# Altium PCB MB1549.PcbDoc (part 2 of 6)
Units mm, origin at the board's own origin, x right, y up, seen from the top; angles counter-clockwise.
Board outline 70 x 133.34 mm, 6 copper layers (Top Layer, Signal Layer 1, Signal Layer 2, Signal Layer 3, Signal Layer 4, Bottom Layer), stack 1.57 mm thick; 289 components, 250 nets, 1288 pads, 875 vias.
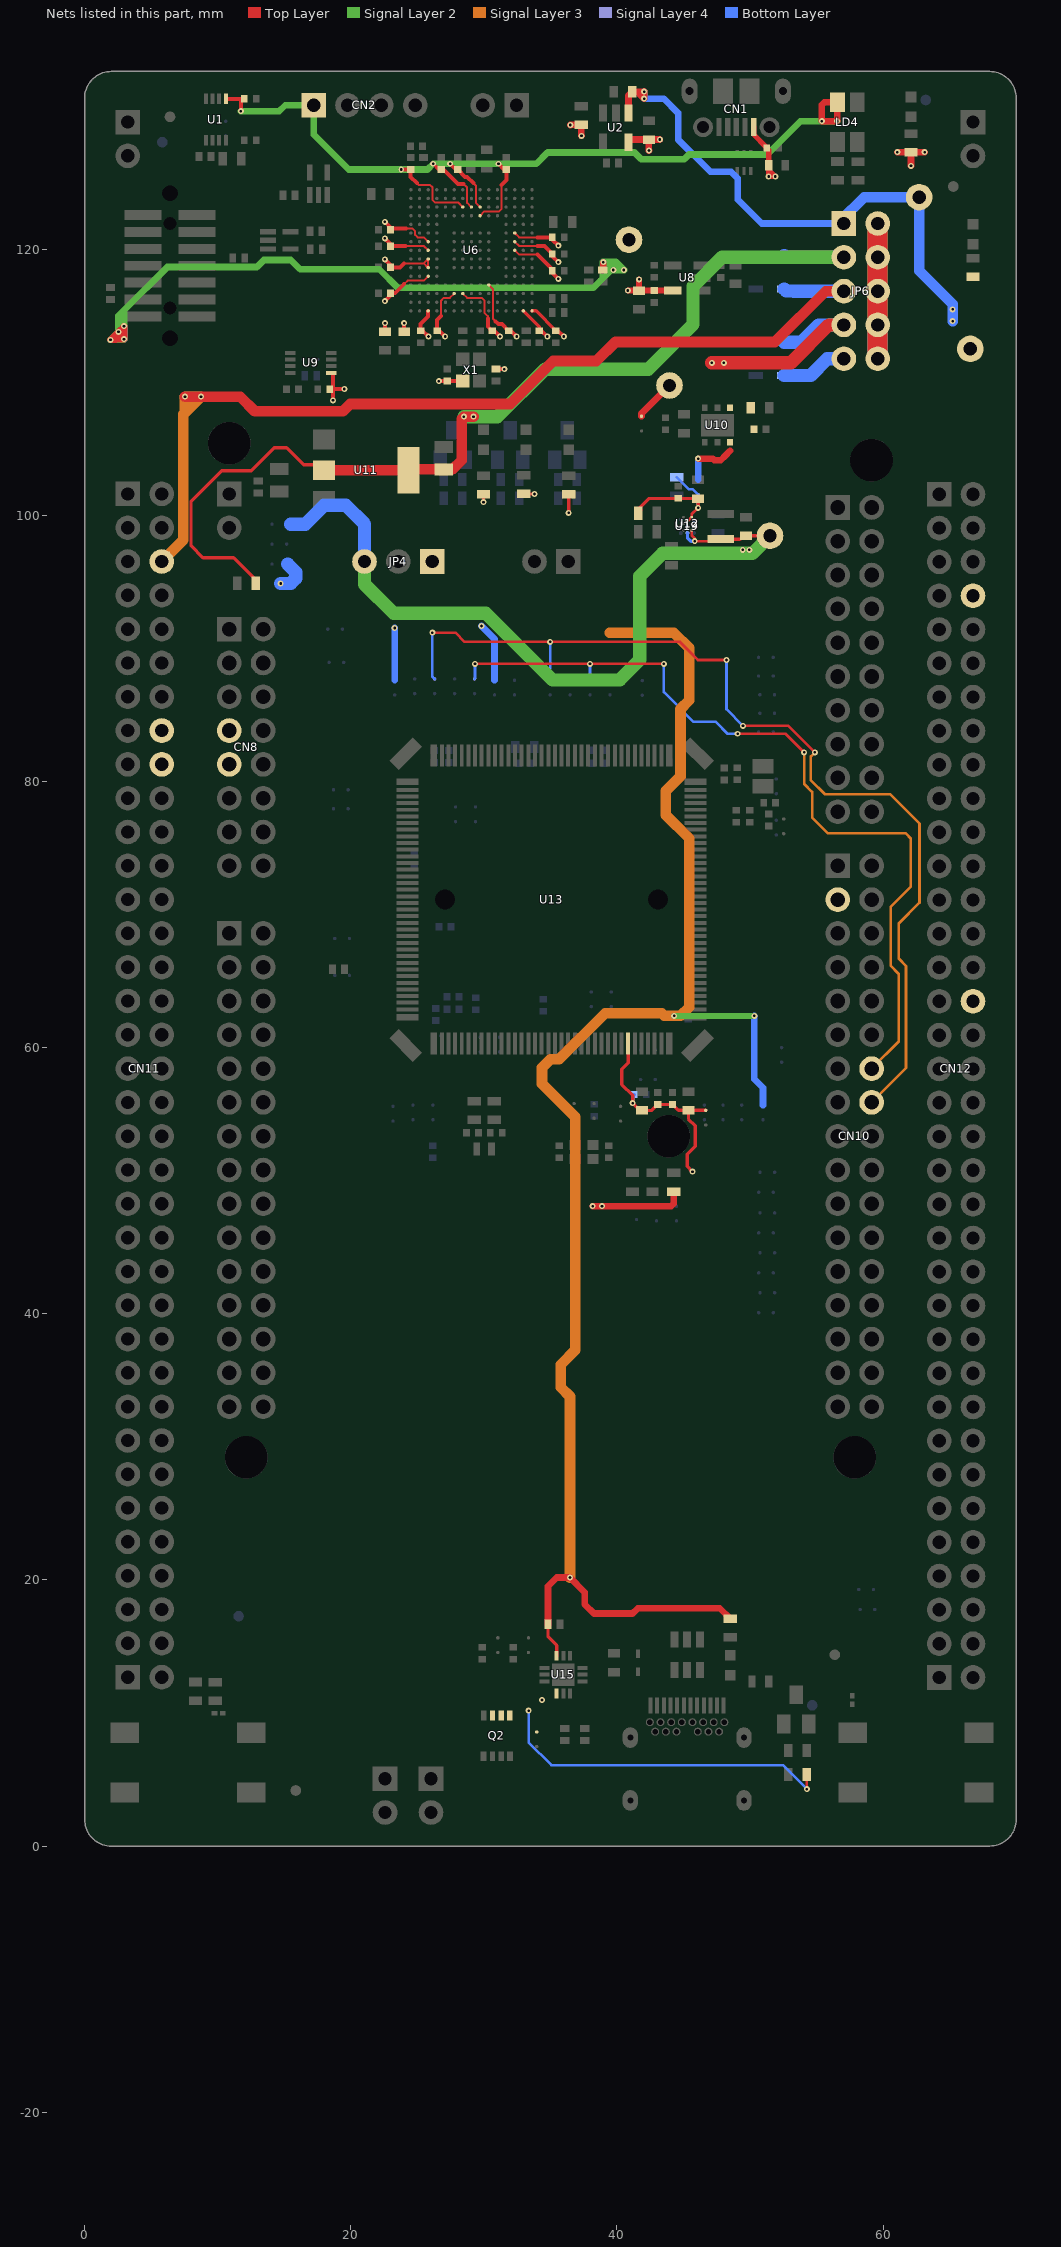
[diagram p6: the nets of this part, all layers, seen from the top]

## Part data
B1: library part MCD-00002, "Non-Open Push-Button 0.1A 24V BLUE", Manufacturer=WEALTHMETAL, Manufacturer_Part_Number=TD0341X-G01-BLU
B2: library part MCD-00001, "Non-Open Push-Button 0.1A 24V BLACK", Manufacturer=WEALTHMETAL, Manufacturer_Part_Number=TD0341X-G01-BLA
C1 C3 C18 C23 C34 C38 C39 C53 C54: library part MCD-00010, "Capacitor, MLCC, 1uF, 16V, X5R, 10%, 0603, T=0,8mm", Manufacturer=YAGEO, Manufacturer_Part_Number=CC0603KRX5R7BB105, Package=C0603
C2 C4 C8 C9 C10 C11 C14 C15 C16 C17 C20 C21 C22 C24 C25 C26 C27 C28 C29 C30 C31 C32 C35 C36 C37 C40 C41 C45 C52 C55 C56 C65 C68 C69 C70 C71 C72 C73 C74 C75 C76 C77 C79 C80 C81 C83 C84: library part MCD-00006, "Capacitor, MLCC, 100nF, 16V, X7R, 10%, 0402, T=0.5mm", Alternate_Manufacturer=MURATA, Alternate_Manufacturer_Part_Number=GCM155R71C104KA55D, Manufacturer=YAGEO, Manufacturer_Part_Number=CC0402KRX7R7BB104, Package=C0402
C5: library part MCD-00016, "Capacitor, MLCC, 20pF, 50V, NPO, 5%, 0402, T=0,5mm", Manufacturer=YAGEO, Manufacturer_Part_Number=CC0402JRNPO9BN200, Package=C0402
C6 C49: library part MCD-00205, "Capacitor, MLCC, 100pF, 50V, NPO, 5%, 0402, T=0,5mm", Manufacturer=YAGEO, Manufacturer_Part_Number=CC0402JRNPO9BN101, Package=C0402
C7 C12 C13: library part MCD-00012, "Capacitor, MLCC, 2.2uF, 10V, X5R, 10%, 0603, T=0,8mm", Alternate_Manufacturer=KEMET, Alternate_Manufacturer_Part_Number=C0603C225K8PACTU, Manufacturer=YAGEO, Manufacturer_Part_Number=CC0603KRX5R6BB225, Package=C0603
C19: library part MCD-00011, "Capacitor, MLCC, 10nF, 16V, X7R, 10%, 0402, T=0.5mm", Manufacturer=YAGEO, Manufacturer_Part_Number=CC0402KRX7R7BB103, Package=C0402
C33 C66: library part MCD-00009, "Capacitor, MLCC, 4.7uF, 16V, X5R, 10%, 0603, T=0.8mm", Manufacturer=YAGEO, Manufacturer_Part_Number=CC0603KRX5R7BB475, Package=C0603
C42 C43: library part MCD-00014, "Capacitor, MLCC, 10uF, 25V, X5R, 10%, 0805, T=0,85mm", Manufacturer=YAGEO, Manufacturer_Part_Number=CC0805KRX5R8BB106, Package=C0805
C44 C46: library part MCD-00243, "Capacitor, MLCC, 10uF, 6V3, X5R, 10%, 0603, T=0,8mm", Manufacturer=YAGEO, Manufacturer_Part_Number=CC0603KRX5R5BB106, Package=C0603
C47 C48 C78 C82: library part MCD-01823, "Capacitor,MLCC,2.2uF,6V3,X5R,10%,0402,T=0.5", Manufacturer=MURATA, Manufacturer_Part_Number=GRM155R60J225KE95D, Package=C0402
C50 C51 C67: library part MCD-01355, "Capacitor, MLCC, 10uF, 4V, X5R, 20%, 0402, T=0,5mm", Manufacturer=MURATA, Manufacturer_Part_Number=GRM155R60G106ME44, Package=C0402
C57 C58: library part MCD-01599, "Capacitor, MLCC, 1.8pF, 50V, NPO, +/-0.1pF, 0402, T=0.5mm", Manufacturer=YAGEO, Manufacturer_Part_Number=CC0402BRNPO9BN1R3, Package=C0402
C59 C60: library part MCD-00674, "Capacitor, MLCC, 6.8pF, 50V, NPO, +-0.25pF, 0402, T=0.5mm", Manufacturer=YAGEO, Manufacturer_Part_Number=CC0402CRNPO9BN6R8, Package=C0402
C61: library part MCD-00637, "Capacitor, MLCC, 10pF, 50V, NPO, 5%, 0603, T=0,8mm", Manufacturer=YAGEO, Manufacturer_Part_Number=CC0603JRNPO9BN100, Package=C0603
C62 C63: library part MCD-01579, "Capacitor, MLCC, 330pF, 50V, NPO, +/-5%, 0402, T=0,5mm", Manufacturer=YAGEO, Manufacturer_Part_Number=CC0402JRNPO9BN331, Package=C0402
C64: library part MCD-01099, "Capacitor,100nF,50V,X7R,10%,0603", Manufacturer=YAGEO, Manufacturer_Part_Number=CC0603KRX7R9BB104, Package=C0603
CN1: library part MCD-00028, "USB-MICRO-B, 0.65mm, RA, SMT, Bottom Mount,", Manufacturer=MOLEX, Manufacturer_Part_Number=1050170001
CN2: library part MCD-00029, "Header, 4x1, 2,54mm, VR, TH, Height 5.84mm/2.54mm", Manufacturer=SAMTEC, Manufacturer_Part_Number=TSW-104-07-x-S
CN3 CN4 CN13 CN14: library part MCD-00214, "Header, 2x1, 2,54mm, VR, TH, Height 5.84mm/10.16mm", Manufacturer=SAMTEC, Manufacturer_Part_Number=TSW-102-09-x-S
CN5: library part MCD-01226, "Header 5x2, 1.27mm, Dual row, Straight, Surface mount, vertical male connector. 3.05mm lead. Mates with FFSD connector. Footprint compatible with FTSH-107-01-L-DV,-K,-A,-P,-ES (STDC14 MEDIUM)", Alternate_Manufacturer=JIUBABA, Alternate_Manufacturer_Part_Number=P127B-2x05MGF-079-1A, Manufacturer=SAMTEC, Manufacturer_Part_Number=FTSH-105-01-L-DV-K
CN7: library part MCD-01039, "Socket, 10x2, 2.54mm, VR, TH, Height 8.51mm/10mm, Low insertion force.", Manufacturer=SAMTEC, Manufacturer_Part_Number=SSW-110-23-x-D
CN8: library part MCD-01037, "Socket, 8x2, 2.54mm, VR, TH, Height 8.51mm/10mm, Low insertion force.", Manufacturer=SAMTEC, Manufacturer_Part_Number=SSW-108-23-x-D
CN9: library part MCD-01040, "Socket, 15x2, 2.54mm, VR, TH, Height 8.51mm/10mm, Low insertion force.", Manufacturer=SAMTEC, Manufacturer_Part_Number=SSW-115-23-x-D
CN10: library part MCD-01041, "Socket, 17x2, 2.54mm, VR, TH, Height 8.51mm/10mm, Low insertion force", Manufacturer=SAMTEC, Manufacturer_Part_Number=SSW-117-23-x-D
CN11 CN12: library part MCD-01210, "Header, 35x2, 2,54mm, VR, TH, Height 5.84mm/2.54mm", Manufacturer=SAMTEC, Manufacturer_Part_Number=TSW-135-07-G-D
CN15: library part MCD-01108, "USB tyce C certified receptacle for 1.6mm pcb height", Manufacturer="CHANT SINCERE (COXOC)", Manufacturer_Part_Number=317JD24BZTF3K3C3
D1: library part MCD-01677, "Small signal Schottky diodes", Manufacturer=STMICROELECTRONICS, Manufacturer_Part_Number=BAT54KFILM, Package=SOD-523
D2 D3 D4 D5: library part MCD-00034, Manufacturer=STMICROELECTRONICS
HW101: library part MCD-00235, "Sticker to mention board reference + serial number", Manufacturer=n/a
HW102: library part MCD-00547, "Sticker to mention board CPN code", Manufacturer=n/a
JP1 JP7 JP8: library part MCD-00045, "Header, 2x1, 2,54mm, VR, TH, Height 5.84mm/2.54mm", Alternate_Manufacturer="JIUBABA; LIANYI", Alternate_Manufacturer_Part_Number=313102S111116;313102S111116, Manufacturer=SAMTEC, Manufacturer_Part_Number=TSW-102-07-x-S
JP2: library part MCD-00683, "Header, 2x1, 2,54mm, VR, TH, Height 5.84mm/2.54mm - Shunt Fitted by default", Alternate_Manufacturer=LIANYI, Alternate_Manufacturer_Part_Number=313102S111116, Manufacturer=SAMTEC, Manufacturer_Part_Number=TSW-102-07-x-S
JP4: library part MCD-00684, "Header, 3x1, 2,54mm, VR, TH, Height 5.84mm/2.54mm - Shunt Fitted 1-2 by default", Manufacturer=SAMTEC, Manufacturer_Part_Number=TSW-103-07-F-S
JP5: library part MCD-00683, "Header, 2x1, 2,54mm, VR, TH, Height 5.84mm/2.54mm - Shunt Fitted by default", Manufacturer=SAMTEC, Manufacturer_Part_Number=TSW-102-07-x-S
JP6: library part MCD-01203, "Header, 5x2, 2,54mm, VR, TH, Height 5.84mm/2.54mm - Shunt Fitted 1-2", Manufacturer=SAMTEC, Manufacturer_Part_Number=TSW-105-07-x-D
L1: library part MCD-00240, "FIXED IND 2.2UH 2.6A 100 mOHM 20% SMD", Manufacturer=TDK, Manufacturer_Part_Number=VLS252010HBX-2R2M-1
L2: library part MCD-01060, "Inductor, 2.2uH, 20%, Isat 0.7A, DCR 0.156Ohm, 0805", Manufacturer=MURATA, Manufacturer_Part_Number=LQM21PN2R2MGH, Package=L0805
LD1 LD5 LD7: library part MCD-00050, "LED, Green, 0603", Manufacturer=EVERLIGHT, Manufacturer_Part_Number=19-213SYGC/S530-E2/TR8, Package="LED 0603"
LD2: library part MCD-00584, "LED Blue, 0603 SMD, 3.3 V Forward Voltage", Manufacturer=VISHAY, Manufacturer_Part_Number=VLMB1300-GS08, Package="LED 0603"
LD3 LD6: library part MCD-00049, "LED, Red, 0603", Manufacturer=EVERLIGHT, Manufacturer_Part_Number=19-213-R6C-AP1Q2B/3T, Package="LED 0603"
LD4: library part MCD-00051, "LED Bicolor", Alternate_Manufacturer=EVERLUCK, Alternate_Manufacturer_Part_Number=LE-RGW35280, Manufacturer="AVAGO TECHNOLOGIES", Manufacturer_Part_Number=HSMF-A201-A00J1
Q1 Q3 Q4 Q5: library part MCD-00073, "NPN Bipolar Transistor", Manufacturer=NXP, Manufacturer_Part_Number=BSR14
Q2: library part MCD-01810, "N-channel 30 V, 6 mΩ typ, 11 A STripFET™ H6, Power MOSFET in a PowerFLAT™ 3.3x3.3 package", Manufacturer=STMICROELECTRONICS, Package="PowerFLAT 3.3x3.3"
R1 R4 R38 R45 R46 R47: library part MCD-00223, "Resistor,100K,0603,1%,1/10W", Manufacturer=YAGEO, Manufacturer_Part_Number=RC0603FR-07100KL, Package=R0603
R2 R14 R24 R30: library part MCD-00070, "Resistor,1K,0603,1%,1/10W", Manufacturer=YAGEO, Manufacturer_Part_Number=RC0603FR-071KL, Package=R0603
R3 R10 R11 R12 R13 R26: library part MCD-00481, "Resistor,47R,0402,1%,1/16W", Manufacturer=YAGEO, Manufacturer_Part_Number=RC0402FR-0747RL, Package=R0402
R5 R17 R20 R44: library part MCD-00067, "Resistor,100R,0402,1%,1/16W", Manufacturer=YAGEO, Manufacturer_Part_Number=RC0402FR-07100RL, Package=R0402
R6: library part MCD-00185, "Resistor,3K,0402,1%,1/16W", Manufacturer=YAGEO, Manufacturer_Part_Number=RC0402FR-073KL, Package=R0402
R7 R8 R39: library part MCD-00197, "Resistor,330R,0603,1%,1/10W", Manufacturer=YAGEO, Manufacturer_Part_Number=RC0603FR-07330RL, Package=R0603
R9 R21 R22 R31 R37 R40: library part MCD-00053, "Resistor,10K,0402,1%,1/16W", Manufacturer=YAGEO, Manufacturer_Part_Number=RC0402FR-0710KL, Package=R0402
R15 R18 R19: library part MCD-00065, "Resistor,4K7,0402,1%,1/16W", Alternate_Manufacturer=YAGEO, Alternate_Manufacturer_Part_Number=RT0402FRE074K7L, Manufacturer_Part_Number=RC0402FR-074K7L, Package=R0402
R16 R41: library part MCD-00055, "Resistor,2K7,0402,1%,1/16W", Manufacturer=YAGEO, Manufacturer_Part_Number=RC0402FR-072K7L, Package=R0402
R23: library part MCD-00508, "Resistor,680R,0603,1%,1/10W", Manufacturer=YAGEO, Manufacturer_Part_Number=RC0603FR-07680RL, Package=R0603
R25 R36: library part MCD-00225, "Resistor,510R,0603,1%,1/10W", Manufacturer=YAGEO, Manufacturer_Part_Number=RC0603FR-07510RL, Package=R0603
R27 R28 R32 R33 R48 R52: library part MCD-00056, "Resistor,0R,0603,5%,1/10W", Manufacturer=YAGEO, Manufacturer_Part_Number=RC0603JR-070RL, Package=R0603
R29: library part MCD-00242, "Resistor,19K6,0603,1%,1/10W", Manufacturer=YAGEO, Manufacturer_Part_Number=RC0603FR-0719K6L, Package=R0603
R34: library part MCD-01171, "Resistor,49K9,0603,1%", Manufacturer=YAGEO, Manufacturer_Part_Number=RC0603FR-0749K9L, Package=R0603
R35: library part MCD-00458, "Resistor,330K,0603,1%,1/10W", Manufacturer=YAGEO, Manufacturer_Part_Number=RC0603FR-07330KL, Package=R0603
R42: library part MCD-00430, "Resistor,22K,0603,1%,1/10W", Manufacturer=YAGEO, Manufacturer_Part_Number=RC0603FR-0722KL, Package=R0603
R43 R49 R50 R51: library part MCD-00222, "Resistor,47K,0603,1%,1/10W", Manufacturer=YAGEO, Manufacturer_Part_Number=RC0603FR-0747KL, Package=R0603
SB1 SB2 SB3 SB4 SB5 SB6 SB7 SB8 SB9 SB10 SB13 SB14 SB15 SB16 SB17 SB18 SB19 SB20 SB21 SB22 SB23 SB24 SB25 SB26 SB27 SB28 SB29 SB30 SB31 SB32 SB33 SB34 SB35 SB36 SB37 SB38 SB39 SB40 SB41 SB42 SB43 SB44 SB45 SB46 SB47 SB48 SB49 SB50 SB51 SB52 SB53 SB54 SB55 SB56 SB57 SB58 SB59 SB60 SB61 SB62 SB63 SB64 SB65 SB66 SB67 SB68 SB69 SB70 SB71 SB72 SB73: library part MCD-00071, "Solder Bridge ON"
SB11 SB12: library part MCD-00071, "Solder Bridge ON", Manufacturer=YAGEO, Manufacturer_Part_Number=RC0603JR-070RL, Package=SB0603
TP1 TP2 TP3 TP4 TP5: library part MCD-01506, "Test Point trought hole 1mm/2mm", Manufacturer=N/A
U1 U9: library part MCD-00264, "Dual bit dual supply bus transceiver", Manufacturer="TEXAS INSTRUMENTS"
U2: library part MCD-02309, "Power Switch, 5V, 0.85A, RDSon 130mOhm max, with active High enable pin and resistor discharge", Alternate_Manufacturer=N/A, Manufacturer="TEXAS INSTRUMENTS", Manufacturer_Part_Number=TPS2051CDBVT, Package=SOT23_5p
U3: library part MCD-00649, "Common mode filter with ESD protection for USB 2.0 interface", Manufacturer=STMICROELECTRONICS
U4: library part MCD-00251, "High power transient voltage suppressor, 7V breakdown", Manufacturer=STMICROELECTRONICS, Manufacturer_Part_Number=ESDA7P60-1U1M
U5 U7: library part MCD-00136, "Dual Transil array for ESD protection", Manufacturer=STMICROELECTRONICS
U6: library part MCD-00596, "STM32F723IEK  (STM32F7) BGA176", Manufacturer=STMICROELECTRONICS, Manufacturer_Part_Number=STM32F723IEK6
U8: library part MCD-00086, "Ultra low drop-low noise BiCMOS voltage, regulators low ESR capacitors compatible", Manufacturer=STMICROELECTRONICS
U10: library part MCD-00215, "Low quiescent current and low noise voltage regulators", Manufacturer=STMICROELECTRONICS, Manufacturer_Part_Number=LD39050PU33R, Package="DFN6 3x3mm"
U11: library part MCD-00088, "IC REG LDO 5V 0.8A SOT223", Manufacturer=STMICROELECTRONICS, Manufacturer_Part_Number=LD1117S50TR, Package=SOT-223
U12: library part MCD-00228, "400mA Nano-Quiescent Step down converter", Manufacturer=STMICROELECTRONICS, Manufacturer_Part_Number=ST1PS01EJR
U13: library part MCD-02503, "MCU, Arm® Cortex®-M33 + FPU, 4MB Flash, 2.5MB SRAM, SMPS", Manufacturer=STMICROELECTRONICS, Manufacturer_HQ_COO=EU, Manufacturer_Part_Number="STM32U575ZIT6Q (IC149-144-145-B5)", Package=LQFP144
U14: library part MCD-00163, "Very low capacitance ESD protection", Manufacturer=STMICROELECTRONICS
U15: library part MCD-01809, "USB Type-C Port Protection for USB Power Delivery, PPS compliant", Manufacturer=STMICROELECTRONICS, Package=QFN-12L
U16: library part MCD-01207, "High power Transient voltage suppressor:25V/35A EOS and ESD transients protection.", Manufacturer=STMICROELECTRONICS, Manufacturer_Part_Number=ESDA25P35-1U1M, Package=QFN1610
U17 U18: library part MCD-00170, "ESD protection 6V1", Manufacturer=STMICROELECTRONICS, Manufacturer_Part_Number=ESDALC6V1-1U2
U19: library part MCD-00226, "UL Step down regulator: Opt0", Manufacturer="ANALOG DEVICES", Manufacturer_Part_Number=ADP5301ACBZ-2-R7
X1: library part MCD-00597, "Oscillator 25Mhz, +-50ppm, Vcc:3.3V typ, square wave: [0.1Vcc;0.9Vcc], Enable pin, SMD", Alternate_Manufacturer=NDK, Alternate_Manufacturer_Part_Number="NZ2520SB 25MHz END4869B", Manufacturer_Part_Number="NZ2520SH 25MHz END4869C"
X2: library part MCD-02291, "Crystal 32.768kHz, 9pF, -+20ppm, 70Kohm max, SMD", Alternate_Manufacturer=N/A, Manufacturer=NDK, Manufacturer_Part_Number="NX1610SE 32.768KHz EXS00A-MU01499", Package=NX1610SE
X3: library part MCD-01476, "Crystal 16 MHz, 8pF, -+20 PPM, R=200Ω, SMD", Manufacturer=NDK, Manufacturer_Part_Number="NX2016SA 16 MHz EXS00A-CS07826", Package=NX2016SA

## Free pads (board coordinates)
  round 3.2 hole 3.2 unplated: 0(10.866,105.409) 0(12.14,29.211) 0(43.89,53.341) 0(57.86,29.211) 0(59.126,104.139)

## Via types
v1: diameter 0.45, hole 0.2, Top Layer to Bottom Layer, tented both sides, 875 vias

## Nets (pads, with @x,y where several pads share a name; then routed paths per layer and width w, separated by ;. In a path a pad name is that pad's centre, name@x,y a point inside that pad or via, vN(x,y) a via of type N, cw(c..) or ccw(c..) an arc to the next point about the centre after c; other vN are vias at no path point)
1V8: C46.2 JP4.3 L1.2 SB16.1 TP5.1 U12.E3 U19.C2 | length 60.7
  Top Layer w0.152: L1.2@47.592,98.313 47.64,98.361 L1.2@47.676,98.396
  Top Layer w0.2: U12.E3@45.619,98.856 45.619,98.481 45.843,98.257 v1(45.843,98.053) 47.642,98.053 L1.2@47.795,98.206
  Top Layer w0.25: L1.2@47.795,98.206 49.245,98.206 49.495,98.456 C46.2@49.695,98.456 TP5.1@51.495,98.456
  Signal Layer 2 w1: JP4.3@21.03,96.521 21.03,94.821 23.222,92.629 30.146,92.629 35.15,87.625 40.2,87.625 41.7,89.125 41.7,95.425 43.425,97.15 49.45,97.15 49.95,97.15 50.189,97.15 50.194,97.156 TP5.1@51.495,98.456
  Bottom Layer w0.25: U19.C2@45.295,98.656 45.295,98.319 45.56,98.053 v1(45.843,98.053)
  Bottom Layer w1: 15.5,99.332 16.582,99.332 18,100.75 19.625,100.75 21.03,99.345 JP4.3@21.03,96.521
  other v1: 49.45,97.4 49.95,97.4
3V3: CN8.7 CN11.16 JP4.1 R23.1 R24.1 R25.2 R36.1 R37.2 SB1.2 SB18.1 SB29.1 SB30.1 SB54.1 TP4.1 U15.12 | length 139.4
  Top Layer w0.25: v1(29.97,100.981) R24.1@29.97,101.581 ; R23.1@33,101.6 v1(33.8,101.6) ; R37.2@34.82,16.431 34.82,15.731 35.47,15.081 U15.12@35.47,14.306 ; v1(36.37,100.181) R25.2@36.37,101.581
  Top Layer w0.5: R37.2@34.82,16.681 34.82,19.531 35.47,20.181 v1(36.47,20.181) 37.57,19.081 37.57,18.181 38.27,17.481 41.17,17.481 41.57,17.881 47.72,17.881 R36.1@48.52,17.081 ; SB1.2@41.845,107.431 41.845,107.645 TP4.1@43.95,109.75
  Signal Layer 2 w0.45: v1(44.3,62.386) v1(50.325,62.386)
  Signal Layer 3 w0.8: v1(36.47,20.181) 36.47,33.781 35.77,34.481 35.77,36.181 36.87,37.281 36.87,54.781 34.37,57.281 34.37,58.481 35.01,59.121 35.648,59.121 39.108,62.581 43.37,62.581 43.565,62.386 v1(44.3,62.386) 44.775,62.386 45.422,63.033 45.422,75.729 43.67,77.481 43.67,79.281 44.77,80.381 44.77,85.445 45.422,86.097 45.422,90.028 44.269,91.181 39.47,91.181
  Bottom Layer w0.5: SB30.1@23.3,87.6 v1(23.3,91.525) ; v1(29.825,91.675) 30.8,90.7 SB29.1@30.8,87.6 ; v1(50.325,62.386) 50.325,57.626 50.97,56.981 SB54.1@50.97,55.681
  Bottom Layer w1: v1(14.725,94.875) 15.5,94.875 15.875,95.25 15.875,95.725 SB18.1@15.268,96.332
3V3_STLK: C2.2 C8.2 C9.2 C10.2 C11.2 C14.2 C15.2 C16.2 C17.2 C21.2 C22.2 C23.2 C24.2 C25.2 C26.2 C27.2 C29.2 C30.2 C31.2 C32.2 C33.2 C34.2 C35.2 C37.2 CN2.1 LD4.4 R22.2 TP2.1 U1.1 U6.C1 U6.C5 U6.C6 U6.C7 U6.C8 U6.C9 U6.F3 U6.G3 U6.G13 U6.H13 U6.J12 U6.J13 U6.K4 U6.N8 U6.N9 U6.N10 U6.P1 U6.R1 U8.5 U9.1 X1.4 | length 142.1
  Top Layer w0.15: 23.996,118.924 25.486,118.924 U6.C7@25.816,119.254 25.816,118.634 U6.C6@25.825,118.625 ; 24.016,117.379 24.271,117.634 25.496,117.634 U6.C5@25.816,117.954 ; 24.116,120.229 25.491,120.229 U6.C8@25.816,119.904 ; 24.141,121.529 24.644,121.529 24.836,121.337 24.836,121.059 25.016,120.879 25.491,120.879 U6.C9@25.816,120.554 ; 24.966,124.954 25.091,124.829 25.941,124.829 26.146,124.624 26.146,123.671 26.339,123.479 28.091,123.479 U6.G13@28.416,123.154 ; 25.471,118.916 25.8,118.588 U6.C6@25.801,118.586 ; 26.791,114.979 26.791,116.131 26.984,116.324 27.436,116.324 U6.F3@27.766,116.654 ; U6.G3@28.416,116.654 28.736,116.334 29.839,116.334 30.036,116.137 30.036,115.209 30.291,114.954 30.291,114.779 ; 28.466,124.904 28.746,124.624 28.746,123.474 U6.H13@29.066,123.154 ; 29.216,124.954 29.396,124.774 29.396,123.474 U6.J13@29.716,123.154 ; U6.J12@29.716,122.504 30.041,122.829 31.144,122.829 31.336,123.021 31.336,124.799 31.341,124.804 ; U6.K4@30.366,117.304 30.686,116.984 30.686,114.759 30.891,114.554 ; U6.N8@32.316,119.904 32.641,119.579 34.041,119.579 ; U6.N9@32.316,120.554 32.641,120.229 34.041,120.229 ; U6.N10@32.316,121.204 32.641,120.879 34.041,120.879
  Top Layer w0.25: U6.P1@32.966,115.354 34.166,114.154 C31.2@34.166,113.854 ; U6.R1@33.616,115.354 33.916,115.354 C32.2@35.416,113.854
  Top Layer w0.3: U1.1@10.616,131.279 11.741,131.279 v1(11.741,130.354) ; U9.1@18.541,110.704 18.666,110.579 C37.2@18.666,109.479 ; v1(18.666,108.629) C37.2@18.666,109.479 ; v1(19.516,109.479) C37.2@18.666,109.479 ; v1(22.562,116.083) 22.991,116.512 C25.2@22.991,116.679 23.316,116.679 24.016,117.379 ; v1(22.562,119.225) 22.991,118.796 C21.2@22.991,118.629 23.701,118.629 23.996,118.924 ; v1(22.562,120.8) 22.991,120.371 C16.2@22.991,120.204 23.016,120.229 24.116,120.229 ; v1(22.562,122.05) 22.991,121.621 C14.2@22.991,121.454 23.066,121.529 24.141,121.529 ; C33.2@22.566,113.779 v1(22.566,114.429) ; v1(23.791,125.979) C8.2@24.491,125.979 24.491,125.429 24.966,124.954 ; C34.2@24.016,113.779 v1(24.016,114.429) ; U6.C1@25.816,115.354 25.816,114.929 25.241,114.354 C26.2@25.241,113.854 25.408,113.854 v1(25.837,113.425) ; v1(26.195,126.408) 26.624,125.979 C9.2@26.791,125.979 26.966,125.979 28.041,124.904 28.466,124.904 ; v1(26.616,110.079) C35.2@27.241,110.079 X1.4@28.416,110.079 ; 26.791,114.979 26.491,114.679 C27.2@26.491,113.854 26.658,113.854 v1(27.087,113.425) ; v1(27.47,126.408) 27.899,125.979 C10.2@28.041,125.979 ; C10.2@28.066,125.979 C10.2@28.041,125.979 ; 29.216,124.954 28.741,125.429 28.579,125.429 28.041,125.967 C10.2@28.041,125.979 ; 30.291,114.779 30.291,114.179 C29.2@30.616,113.854 30.783,113.854 v1(31.212,113.425) ; 30.891,114.554 31.086,114.359 31.361,114.359 C30.2@31.866,113.854 32.033,113.854 v1(32.462,113.425) ; R22.2@30.916,110.979 v1(31.541,110.979) ; v1(31.095,126.408) 31.524,125.979 C11.2@31.691,125.979 31.716,125.954 31.716,125.179 31.341,124.804 ; 34.041,119.579 35.141,118.479 C22.2@35.141,118.379 C22.2@35.166,118.354 ; 34.041,120.229 34.541,120.229 C17.2@35.141,119.629 C17.2@35.166,119.604 ; 34.041,120.879 C15.2@35.141,120.879 C15.2@35.166,120.854 ; C31.2@34.166,113.854 34.333,113.854 v1(34.762,113.425) ; C22.2@35.141,118.354 C22.2@35.166,118.354 ; C17.2@35.141,119.604 C17.2@35.166,119.604 ; C15.2@35.141,120.854 C15.2@35.166,120.854 ; C32.2@35.416,113.854 35.583,113.854 v1(36.012,113.425) ; v1(35.595,117.758) 35.166,118.187 C22.2@35.166,118.354 ; v1(35.595,119.008) 35.166,119.437 C17.2@35.166,119.604 ; v1(35.595,120.258) 35.166,120.687 C15.2@35.166,120.854
  Top Layer w0.45: v1(40.816,116.879) C23.2@41.666,116.879 ; v1(41.666,117.729) C23.2@41.666,116.879 ; U8.5@44.191,116.879 C24.2@42.791,116.879 C23.2@41.666,116.879
  Top Layer w0.5: v1(55.391,129.604) 55.391,130.829 55.591,131.029 LD4.4@56.566,131.029 56.541,131.004 v1(56.541,129.604) v1(55.391,129.604)
  Signal Layer 2 w0.5: v1(11.741,130.354) 14.616,130.354 15.071,130.809 CN2.1@17.216,130.809 17.216,128.604 19.846,125.974 23.791,125.974 25.761,125.974 v1(26.195,126.408) v1(27.47,126.408) v1(31.095,126.408) 33.945,126.408 34.791,127.254 41.316,127.254 41.816,126.754 45.066,126.754 45.411,127.099 51.286,127.099 53.791,129.604 v1(55.391,129.604) v1(56.541,129.604)
5V: C38.2 C41.2 CN8.9 CN11.18 JP6.2 JP6.4 JP6.6 JP6.8 JP6.10 R14.2 R16.1 SB13.1 TP3.1 U10.1 U10.6 | length 105.1
  Top Layer w0.45: v1(2.541,113.779) 2.956,114.194 v1(2.966,114.204)
  Top Layer w0.5: v1(1.941,113.179) v1(2.541,113.779) ; v1@2.956,114.194 2.966,114.194 2.966,113.804 ; R16.1@38.941,118.429 38.975,118.463 v1(38.975,119.02) ; v1(46.095,104.256) 47.177,104.256 47.304,104.13 47.796,104.13 48.145,104.479 48.145,104.495 48.5,104.85 ; 2.391,113.229 2.679,113.516 2.741,113.579 2.966,113.804 ; 2.391,113.229 2.341,113.179 1.954,113.179 2.004,113.229 2.391,113.229 ; 2.391,113.229 v1(2.966,113.229) 2.966,113.779 2.966,113.804
  Top Layer w1.5: JP6.10@59.59,111.759 JP6.8@59.59,114.299 JP6.6@59.59,116.839 JP6.4@59.59,119.379 JP6.2@59.59,121.919
  Signal Layer 2 w0.5: v1(1.941,113.179) v1@1.966,113.179 ; v1@40.541,118.429 v1(40.516,118.429) ; v1@1.966,113.179 1.966,113.204 v1(2.541,113.779) ; v1@1.966,113.179 2.916,113.179 v1(2.966,113.229) v1@2.966,113.354 ; v1(2.541,113.779) 2.541,114.204 2.541,114.979 2.966,115.404 ; v1(2.541,113.779) v1@2.966,113.354 ; v1(2.541,113.779) v1(2.966,114.204) ; v1@2.966,113.354 2.966,113.779 v1(2.966,114.204) ; v1(2.966,114.204) 2.966,115.404 ; 2.966,115.404 6.216,118.654 12.941,118.654 13.466,119.179 15.491,119.179 16.191,118.479 22.141,118.479 23.541,117.079 38.216,117.079 38.941,117.804 ; 38.941,117.804 38.941,118.429 ; 38.941,117.804 v1@39.566,118.429 ; 38.941,118.429 38.941,119.02 v1@38.941,119.054 ; 38.941,118.429 v1@39.566,118.429 ; v1@38.941,119.054 38.975,119.054 39.466,119.054 ; v1@38.941,119.054 v1(38.975,119.02) v1@39.566,118.429 ; 39.466,119.054 39.908,118.612 40.091,118.429 ; 39.466,119.054 39.891,119.054 v1(40.516,118.429) ; v1@39.566,118.429 v1(39.725,118.429) 40.091,118.429 ; 40.091,118.429 v1(40.516,118.429)
  Signal Layer 2 w1.5: JP6.8@59.59,114.299 JP6.6@59.59,116.839 JP6.4@59.59,119.379 JP6.2@59.59,121.919
  Signal Layer 3 w1.5: JP6.10@59.59,111.759 JP6.8@59.59,114.299 JP6.6@59.59,116.839 JP6.4@59.59,119.379 JP6.2@59.59,121.919
  Bottom Layer w0.5: SB13.1@46.095,102.656 v1(46.095,104.256) ; v1(2.541,113.779) 2.541,113.654 v1(2.966,113.229) ; v1(2.541,113.779) v1(1.941,113.179) 2.916,113.179 v1(2.966,113.229) ; v1(2.541,113.779) v1(2.966,114.204) 2.966,113.779 v1(2.966,113.229)
  Bottom Layer w1.5: JP6.10@59.59,111.759 JP6.8@59.59,114.299 ; JP6.8@59.59,114.299 JP6.6@59.59,116.839 JP6.4@59.59,119.379 JP6.2@59.59,121.919
5V_EXT: CN11.6 D3.1 JP6.5 | length 74.3
  Top Layer w0.8: v1(7.541,108.904) v1(8.741,108.904) 11.696,108.904 12.8,107.8 19.4,107.8 19.954,108.354 31.991,108.354 35.221,111.584 38.45,111.584 39.885,113.019 51.856,113.019 55.676,116.839 JP6.5@57.05,116.839
  Signal Layer 3 w0.8: CN11.6@5.79,96.521 7.425,98.156 7.425,107.588 7.541,107.704 ; 7.541,107.704 v1(7.541,108.904) v1(8.741,108.904) 7.541,107.704
  Bottom Layer w1: D3.1@52.57,117 52.72,116.85 53.245,116.85 53.256,116.839 JP6.5@57.05,116.839
5V_SMPS_IN: C44.2 C45.2 R27.2 R48.1 SB13.2 U12.A3 U12.B2 | length 10.3
  Top Layer w0.2: R27.2@41.595,100.456 R27.2@41.595,100.156 R27.2@41.815,100.376 ; U12.B2@45.307,99.606 45.369,99.606 U12.A3@45.619,99.856 45.619,100.08 v1@46.094,100.556
  Top Layer w0.25: R27.2@41.595,100.456 42.395,101.256 44.6,101.256 C44.2@46.095,101.256 v1@46.095,100.556
  Bottom Layer w0.2: R48.1@44.5,102.85 45.4,101.95 45.7,101.95 SB13.2@46.1,101.55
  Bottom Layer w0.25: v1(46.1,100.55) 46.1,101.3
5V_UCPD: D4.1 JP6.7 Q2.1 Q2.2 Q2.3 R35.2 R43.1 SB10.1 U15.4 | length 49.1
  Top Layer w0.2: v1(54.27,4.281) R43.1@54.27,5.381
  Top Layer w0.5: v1(38.17,48.081) v1(38.87,48.081) 44.07,48.081 44.27,48.281 R35.2@44.27,49.181
  Top Layer w1: v1(47.125,111.45) v1(48.025,111.45) 53.075,111.45 55.924,114.299 JP6.7@57.05,114.299
  Bottom Layer w0.2: v1(33.37,10.181) 33.37,7.781 35.07,6.081 52.47,6.081 v1(54.27,4.281)
  Bottom Layer w1: D4.1@52.57,113 53.851,113 55.15,114.299 JP6.7@57.05,114.299
  other v1: 34.37,10.981
5V_USB_CHGR: C3.2 C6.2 CN1.1 D5.1 JP6.9 R1.2 R2.2 U2.5 U4.1 | length 19.5
  Top Layer w0.4: U2.5@40.866,128.014 U2.5@40.866,128.229 ; C3.2@42.394,128.229 C3.2@42.396,128.227 ; CN1.1@50.266,129.158 50.266,128.626 51.249,127.643 C6.2@51.249,127.593 ; C6.2@51.249,127.593 51.399,127.443 U4.1@51.399,126.293 U4.1@51.399,125.946 ; U4.1@51.399,125.946 51.649,125.696 v1(51.899,125.446) v1(51.399,125.446) U4.1@51.399,125.946
  Top Layer w0.5: v1(36.498,129.324) 36.503,129.329 R1.2@37.325,129.329 37.325,128.507 v1(37.33,128.502) ; U2.5@40.866,128.229 C3.2@42.394,128.229 ; v1(42.401,127.401) 42.396,127.406 C3.2@42.396,128.227 43.218,128.227 v1(43.223,128.232) ; v1(61.066,127.279) R2.2@62.091,127.279 ; v1(62.091,126.254) R2.2@62.091,127.279 ; v1(63.116,127.279) R2.2@62.091,127.279
  Signal Layer 4 w0.4: v1(51.399,125.446) v1(51.899,125.446)
  Bottom Layer w0.4: v1(51.399,125.446) v1(51.899,125.446)
  Bottom Layer w1: D5.1@52.57,110.5 54.55,110.5 55.809,111.759 JP6.9@57.05,111.759
5V_USB_STLK: C1.2 CN12.8 JP6.1 TP1.1 U2.1 | length 42.7
  Top Layer w0.508: U2.1@40.866,130.214 40.866,131.537 C1.2@41.148,131.82 ; C1.2@41.148,131.82 41.525,131.82 ; 41.525,131.82 v1@42.041,131.82 ; 41.525,131.82 41.778,131.567 v1(42.041,131.304) v1@42.041,131.82 ; v1@42.041,131.82 42.05,131.82 v1(42.041,131.829) v1@42.041,131.82
  Bottom Layer w0.5: v1(42.041,131.304) 43.516,131.304 44.591,130.229 44.591,128.229 47.016,125.804 48.566,125.804 49.071,125.299 49.071,123.724 50.876,121.919 56.586,121.919 JP6.1@57.05,121.919
  Bottom Layer w0.508: v1(42.041,131.304) v1(42.041,131.829)
  Bottom Layer w0.8: JP6.1@56.586,121.919 56.818,122.151 58.567,123.9 TP1.1@62.7,123.9 62.7,118.375 65.225,115.85 v1(65.225,115.475) v1(65.225,114.575)
5V_VIN: C42.2 D2.1 JP6.3 R30.2 U11.2 U11.4 | length 76.3
  Top Layer w0.25: R30.2@12.883,94.894 12.883,95.117 11.193,96.807 8.893,96.807 8,97.7 8,101.05 10.3,103.35 12.514,103.35 14.245,105.081 15.17,105.081 16.47,103.781 17.58,103.781 U11.2@17.982,103.379
  Top Layer w0.8: U11.2@17.982,103.379 U11.4@24.332,103.379 24.396,103.444 C42.2@26.974,103.444 ; C42.2@26.974,103.444 27.644,103.444 28.325,104.125 28.325,107.225 v1(28.5,107.4) v1(29.225,107.4)
  Signal Layer 2 w1: v1(28.5,107.4) v1(29.225,107.4) 31.012,107.4 34.591,110.979 42.341,110.979 45.716,114.354 45.716,117.204 47.891,119.379 JP6.3@57.05,119.379
  Bottom Layer w1: D2.1@52.57,119.5 52.695,119.375 53.27,119.375 53.274,119.379 JP6.3@57.05,119.379
AGND: C53.2 C54.2 C55.1 C56.1 C65.1 CN10.3 CN12.32 SB7.2 U13.30 | length 17
  Top Layer w0.25: U13.30@40.837,60.296 40.837,58.848 40.37,58.381 40.37,57.225 41.175,56.42 v1(41.175,55.825) 41.719,55.281 C53.2@41.87,55.281 42.62,55.281 C55.1@43.07,55.731 C56.1@44.17,55.731 44.62,55.281 C54.2@45.37,55.281 ; v1(45.67,50.681) 45.27,51.081 45.27,51.981 45.87,52.581 45.87,54.131 45.37,54.631 C54.2@45.37,55.281 ; SB7.2@46.67,55.281 C54.2@45.37,55.281
  Bottom Layer w0.25: v1(41.175,55.825) 41.175,56.35 C65.1@41.3,56.475
ARD_D0_RX: CN10.16 SB27.1 SB33.2 | length 75.7
  Top Layer w0.2: v1(26.125,91.175) 27.85,91.175 28.542,90.483 v1(34.975,90.483) 44.717,90.483 46.075,89.125 v1(48.225,89.125) ; v1(49.47,84.181) 52.87,84.181 v1(54.87,82.181)
  Signal Layer 3 w0.2: v1(54.87,82.181) 54.57,81.881 54.57,80.081 55.611,79.04 60.511,79.04 62.73,76.821 62.73,70.893 61.17,69.333 61.17,66.681 61.718,66.133 61.718,58.469 CN10.16@59.13,55.881
  Bottom Layer w0.2: v1(26.125,91.175) 26.125,87.862 26.138,87.862 SB33.2@26.3,87.7 ; SB27.1@34.975,87.6 v1(34.975,90.483) ; v1(48.225,89.125) 48.225,85.426 v1(49.47,84.181)
ARD_D1_TX: CN10.14 SB25.1 SB31.2 | length 63.3
  Top Layer w0.2: v1(29.331,88.831) v1(37.975,88.831) 37.976,88.83 43.519,88.83 v1(43.52,88.831) ; v1(49.07,83.581) 52.67,83.581 v1(54.07,82.181)
  Signal Layer 3 w0.2: v1(54.07,82.181) 54.07,79.808 54.67,79.208 54.67,77.287 55.857,76.1 61.699,76.1 62.07,75.729 62.07,72.081 60.56,70.571 60.56,66.151 61.17,65.541 61.17,60.461 CN10.14@59.13,58.421
  Bottom Layer w0.2: SB31.2@29.3,87.7 29.331,87.731 v1(29.331,88.831) ; SB25.1@37.975,87.6 v1(37.975,88.831) ; v1(43.52,88.831) 43.52,86.705 45.75,84.475 47.425,84.475 48.319,83.581 v1(49.07,83.581)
